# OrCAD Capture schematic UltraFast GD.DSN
size E
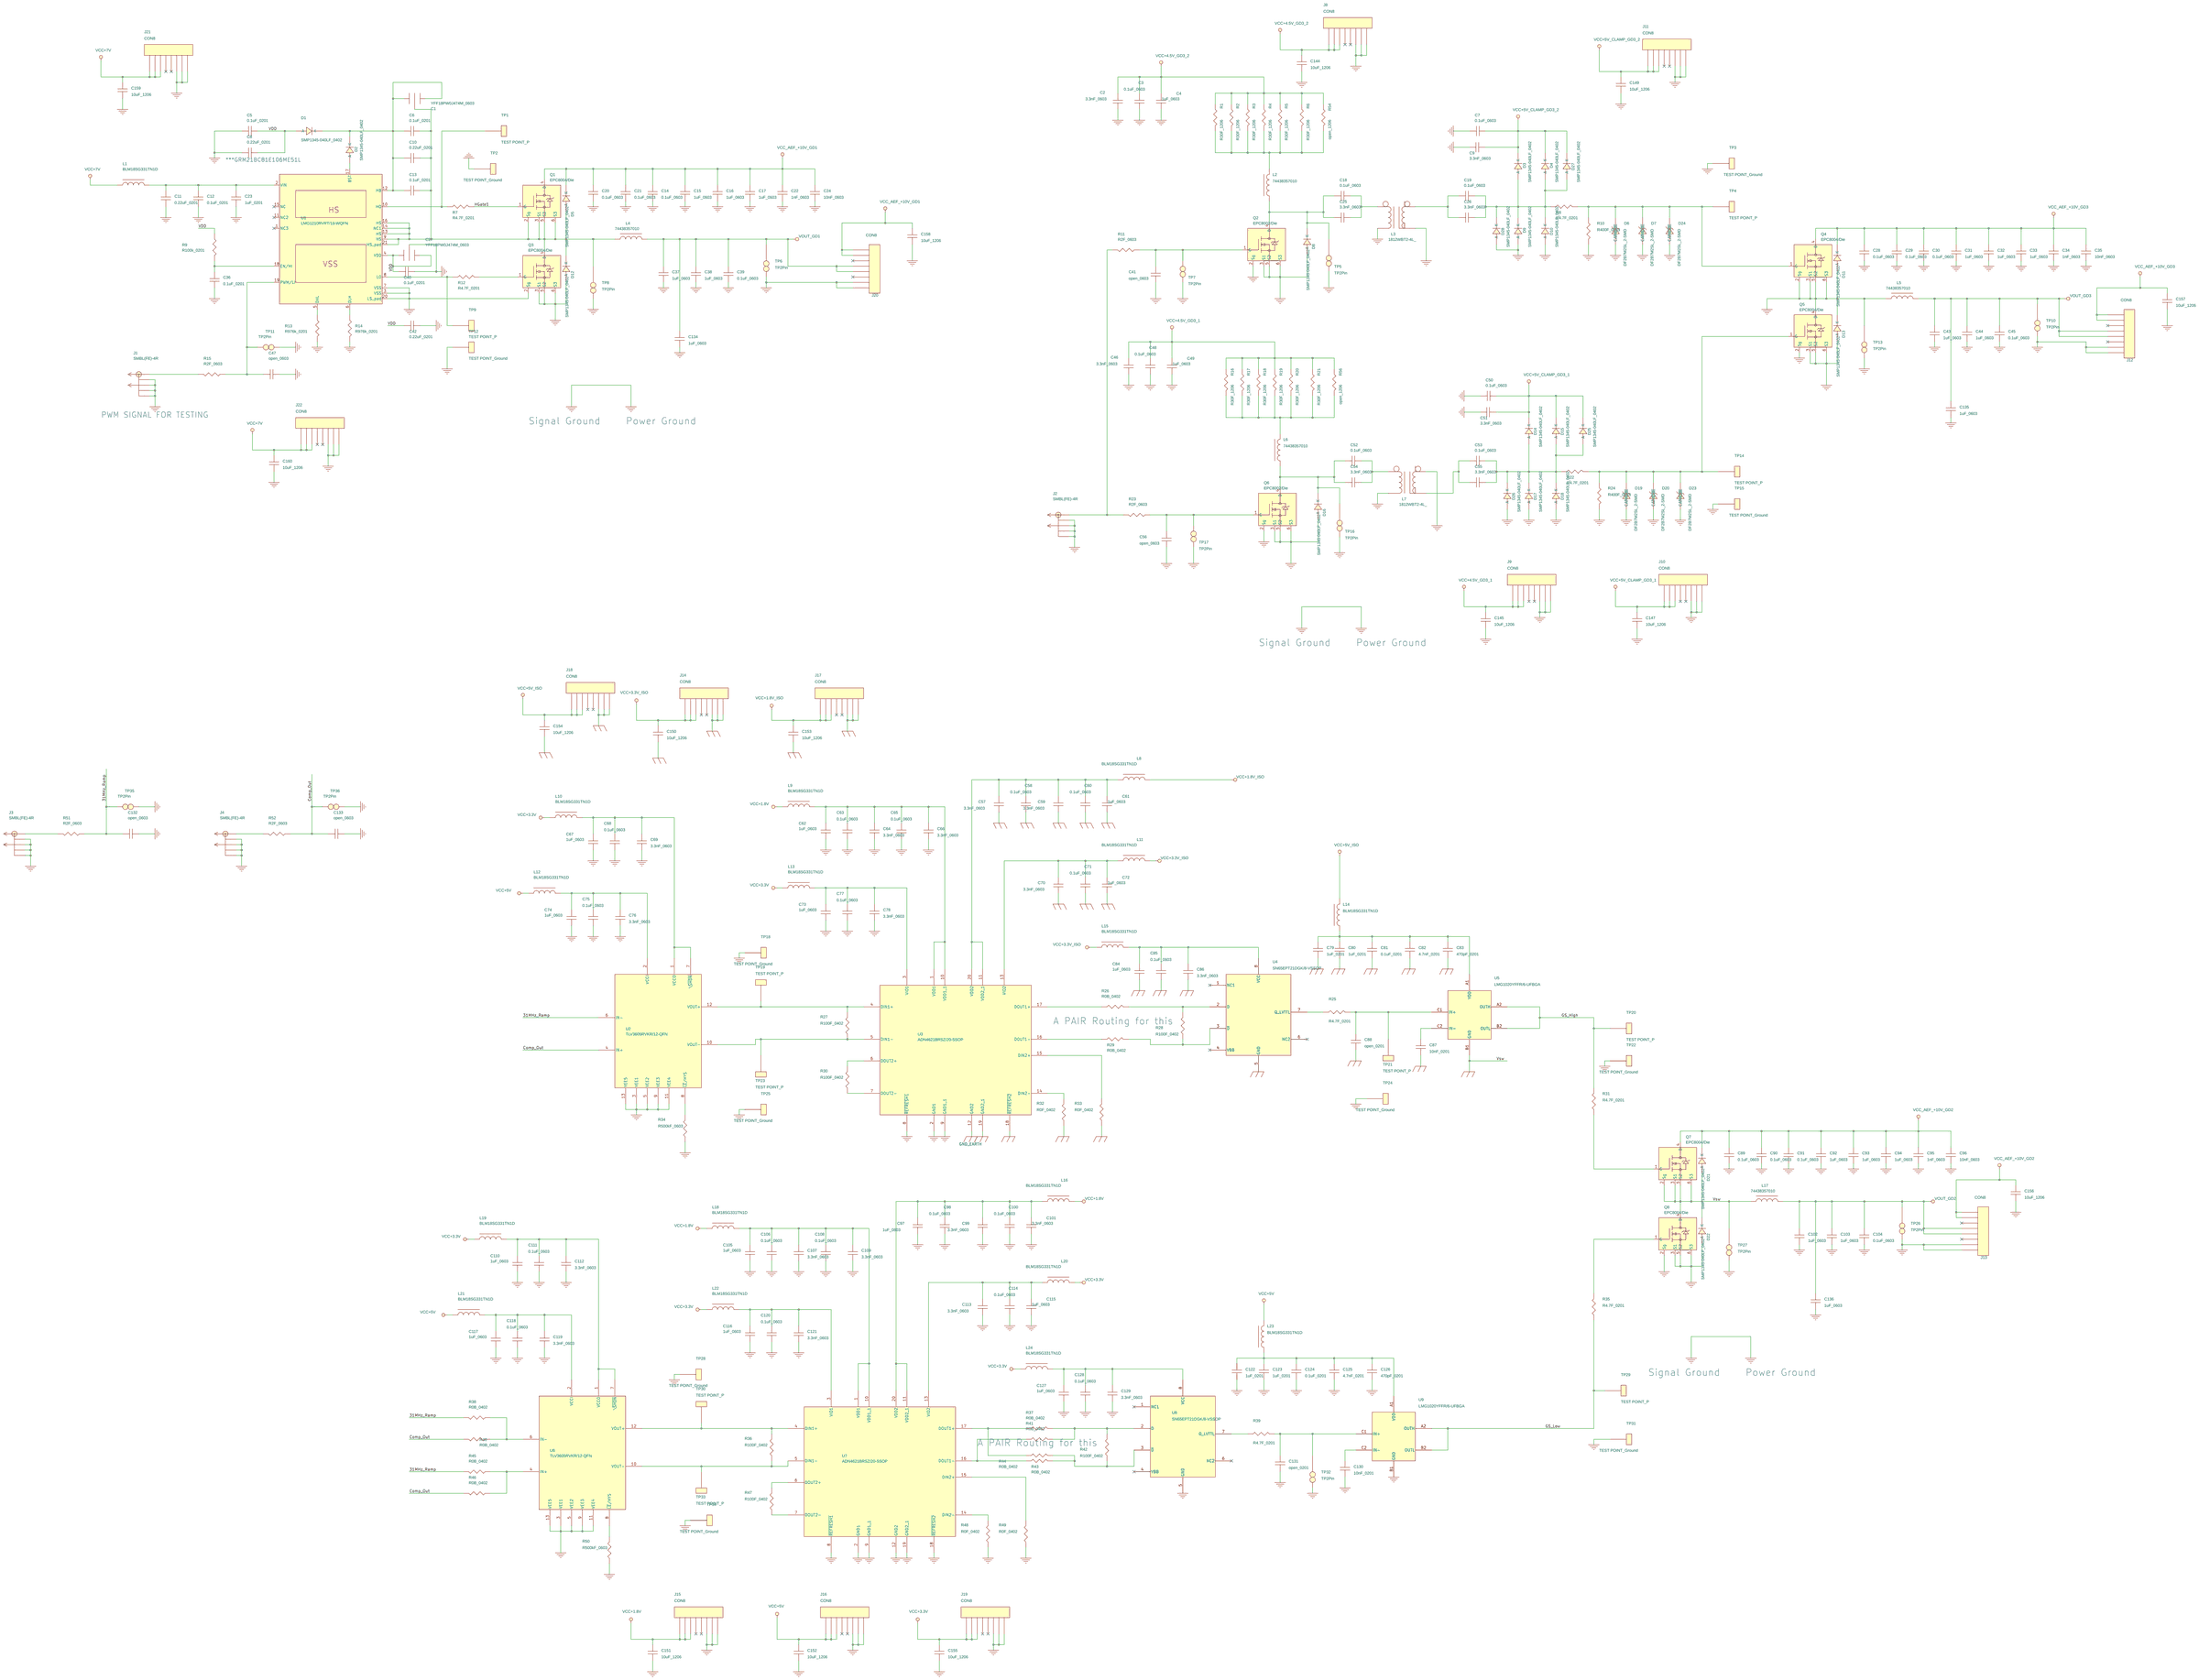
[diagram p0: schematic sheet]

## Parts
C1  YFF18PW0J474M_0603  [FEEDTHRU_0603]
C2  3.3nF_0603  [C1608]
C3  0.1uF_0603  [C1608]
C4  1uF_0603  [C1608]
C5  0.1uF_0201  [C_0201_SHORT]
C6  0.1uF_0201  [C_0201_SHORT]
C7  0.1uF_0603  [C1608]
C8  0.22uF_0201  [C_0201_SHORT]
C9  3.3nF_0603  [C1608]
C10  0.22uF_0201  [C_0201_SHORT]
C11  0.22uF_0201  [C_0201_SHORT]
C12  0.1uF_0201  [C_0201_SHORT]
C13  0.1uF_0201  [C_0201_SHORT]
C14  0.1uF_0603  [C1608]
C15  1uF_0603  [C1608]
C16  1uF_0603  [C1608]
C17  1uF_0603  [C1608]
C18  0.1uF_0603  [C1608]
C19  0.1uF_0603  [C1608]
C20  0.1uF_0603  [C1608]
C21  0.1uF_0603  [C1608]
C22  1nF_0603  [C1608]
C23  1uF_0201  [C_0201_SHORT]
C24  10nF_0603  [C1608]
C25  3.3nF_0603  [C1608]
C26  3.3nF_0603  [C1608]
C27  YFF18PW0J474M_0603  [FEEDTHRU_0603]
C28  0.1uF_0603  [C1608]
C29  0.1uF_0603  [C1608]
C30  0.1uF_0603  [C1608]
C31  1uF_0603  [C1608]
C32  1uF_0603  [C1608]
C33  1uF_0603  [C1608]
C34  1nF_0603  [C1608]
C35  10nF_0603  [C1608]
C36  0.1uF_0201  [C_0201_SHORT]
C37  1uF_0603  [C1608]
C38  1uF_0603  [C1608]
C39  0.1uF_0603  [C1608]
C40  0.1uF_0201  [C_0201_SHORT]
C41  open_0603  [C1608]
C42  0.22uF_0201  [C_0201_SHORT]
C43  1uF_0603  [C1608]
C44  1uF_0603  [C1608]
C45  0.1uF_0603  [C1608]
C46  3.3nF_0603  [C1608]
C47  open_0603  [C1608]
C48  0.1uF_0603  [C1608]
C49  1uF_0603  [C1608]
C50  0.1uF_0603  [C1608]
C51  3.3nF_0603  [C1608]
C52  0.1uF_0603  [C1608]
C53  0.1uF_0603  [C1608]
C54  3.3nF_0603  [C1608]
C55  3.3nF_0603  [C1608]
C56  open_0603  [C1608]
C57  3.3nF_0603  [C1608]
C58  0.1uF_0603  [C1608]
C59  3.3nF_0603  [C1608]
C60  0.1uF_0603  [C1608]
C61  1uF_0603  [C1608]
C62  1uF_0603  [C1608]
C63  0.1uF_0603  [C1608]
C64  3.3nF_0603  [C1608]
C65  0.1uF_0603  [C1608]
C66  3.3nF_0603  [C1608]
C67  1uF_0603  [C1608]
C68  0.1uF_0603  [C1608]
C69  3.3nF_0603  [C1608]
C70  3.3nF_0603  [C1608]
C71  0.1uF_0603  [C1608]
C72  1uF_0603  [C1608]
C73  1uF_0603  [C1608]
C74  1uF_0603  [C1608]
C75  0.1uF_0603  [C1608]
C76  3.3nF_0603  [C1608]
C77  0.1uF_0603  [C1608]
C78  3.3nF_0603  [C1608]
C79  1uF_0201  [C_0201_SHORT]
C80  1uF_0201  [C_0201_SHORT]
C81  0.1uF_0201  [C_0201_SHORT]
C82  4.7nF_0201  [C_0201_SHORT]
C83  470pF_0201  [C_0201_SHORT]
C84  1uF_0603  [C1608]
C85  0.1uF_0603  [C1608]
C86  3.3nF_0603  [C1608]
C87  10nF_0201  [C_0201_SHORT]
C88  open_0201  [C_0201_SHORT]
C89  0.1uF_0603  [C1608]
C90  0.1uF_0603  [C1608]
C91  0.1uF_0603  [C1608]
C92  1uF_0603  [C1608]
C93  1uF_0603  [C1608]
C94  1uF_0603  [C1608]
C95  1nF_0603  [C1608]
C96  10nF_0603  [C1608]
C97  1uF_0603  [C1608]
C98  0.1uF_0603  [C1608]
C99  3.3nF_0603  [C1608]
C100  0.1uF_0603  [C1608]
C101  3.3nF_0603  [C1608]
C102  1uF_0603  [C1608]
C103  1uF_0603  [C1608]
C104  0.1uF_0603  [C1608]
C105  1uF_0603  [C1608]
C106  0.1uF_0603  [C1608]
C107  3.3nF_0603  [C1608]
C108  0.1uF_0603  [C1608]
C109  3.3nF_0603  [C1608]
C110  1uF_0603  [C1608]
C111  0.1uF_0603  [C1608]
C112  3.3nF_0603  [C1608]
C113  3.3nF_0603  [C1608]
C114  0.1uF_0603  [C1608]
C115  1uF_0603  [C1608]
C116  1uF_0603  [C1608]
C117  1uF_0603  [C1608]
C118  0.1uF_0603  [C1608]
C119  3.3nF_0603  [C1608]
C120  0.1uF_0603  [C1608]
C121  3.3nF_0603  [C1608]
C122  1uF_0201  [C_0201_SHORT]
C123  1uF_0201  [C_0201_SHORT]
C124  0.1uF_0201  [C_0201_SHORT]
C125  4.7nF_0201  [C_0201_SHORT]
C126  470pF_0201  [C_0201_SHORT]
C127  1uF_0603  [C1608]
C128  0.1uF_0603  [C1608]
C129  3.3nF_0603  [C1608]
C130  10nF_0201  [C_0201_SHORT]
C131  open_0201  [C_0201_SHORT]
C132  open_0603  [C1608]
C133  open_0603  [C1608]
C134  1uF_0603  [C1608]
C135  1uF_0603  [C1608]
C136  1uF_0603  [C1608]
C144  10uF_1206  [OPEN_1206]
C145  10uF_1206  [OPEN_1206]
C147  10uF_1206  [OPEN_1206]
C149  10uF_1206  [OPEN_1206]
C150  10uF_1206  [OPEN_1206]
C151  10uF_1206  [OPEN_1206]
C152  10uF_1206  [OPEN_1206]
C153  10uF_1206  [OPEN_1206]
C154  10uF_1206  [OPEN_1206]
C155  10uF_1206  [OPEN_1206]
C156  10uF_1206  [OPEN_1206]
C157  10uF_1206  [OPEN_1206]
C158  10uF_1206  [OPEN_1206]
C159  10uF_1206  [OPEN_1206]
C160  10uF_1206  [OPEN_1206]
D1  SMP1345-040LF_0402  [SMP1345-040LF]
D2  SMP1345-040LF_0402  [SMP1345-040LF]
D3  SMP1345-040LF_0402  [SMP1345-040LF]
D4  SMP1345-040LF_0402  [SMP1345-040LF]
D5  SMP1345-040LF_0402  [SMP1345-040LF]
D6  DF2B7M2SL_2-SMD  [DF2B7M3SL_L3F]
D7  DF2B7M2SL_2-SMD  [DF2B7M3SL_L3F]
D8  SMP1345-040LF_0402  [SMP1345-040LF]
D9  SMP1345-040LF_0402  [SMP1345-040LF]
D10  SMP1345-040LF_0402  [SMP1345-040LF]
D11  SMP1345-040LF_0402  [SMP1345-040LF]
D12  SMP1345-040LF_0402  [SMP1345-040LF]
D13  SMP1345-040LF_0402  [SMP1345-040LF]
D14  SMP1345-040LF_0402  [SMP1345-040LF]
D15  SMP1345-040LF_0402  [SMP1345-040LF]
D16  SMP1345-040LF_0402  [SMP1345-040LF]
D17  SMP1345-040LF_0402  [SMP1345-040LF]
D18  SMP1345-040LF_0402  [SMP1345-040LF]
D19  DF2B7M2SL_2-SMD  [DF2B7M3SL_L3F]
D20  DF2B7M2SL_2-SMD  [DF2B7M3SL_L3F]
D21  SMP1345-040LF_0402  [SMP1345-040LF]
D22  SMP1345-040LF_0402  [SMP1345-040LF]
D23  DF2B7M2SL_2-SMD  [DF2B7M3SL_L3F]
D24  DF2B7M2SL_2-SMD  [DF2B7M3SL_L3F]
D25  SMP1345-040LF_0402  [SMP1345-040LF]
D26  SMP1345-040LF_0402  [SMP1345-040LF]
D27  SMP1345-040LF_0402  [SMP1345-040LF]
D28  SMP1345-040LF_0402  [SMP1345-040LF]
J1  SMBL(FE)-4R  [SMBL(FE)-4R]
J2  SMBL(FE)-4R  [SMBL(FE)-4R]
J3  SMBL(FE)-4R  [SMBL(FE)-4R]
J4  SMBL(FE)-4R  [SMBL(FE)-4R]
J8  CON8  [HEADER_8_2.54MM]
J9  CON8  [HEADER_8_2.54MM]
J10  CON8  [HEADER_8_2.54MM]
J11  CON8  [HEADER_8_2.54MM]
J12  CON8  [HEADER_8_2.54MM]
J13  CON8  [HEADER_8_2.54MM]
J14  CON8  [HEADER_8_2.54MM]
J15  CON8  [HEADER_8_2.54MM]
J16  CON8  [HEADER_8_2.54MM]
J17  CON8  [HEADER_8_2.54MM]
J18  CON8  [HEADER_8_2.54MM]
J19  CON8  [HEADER_8_2.54MM]
J20  CON8  [HEADER_8_2.54MM]
J21  CON8  [HEADER_8_2.54MM]
J22  CON8  [HEADER_8_2.54MM]
L1  BLM18SG331TN1D  [L1608]
L2  74438357010  [74438357010]
L3  1812WBT2-4L_  [1812WBT2]
L4  74438357010  [74438357010]
L5  74438357010  [74438357010]
L6  74438357010  [74438357010]
L7  1812WBT2-4L_  [1812WBT2]
L8  BLM18SG331TN1D  [L1608]
L9  BLM18SG331TN1D  [L1608]
L10  BLM18SG331TN1D  [L1608]
L11  BLM18SG331TN1D  [L1608]
L12  BLM18SG331TN1D  [L1608]
L13  BLM18SG331TN1D  [L1608]
L14  BLM18SG331TN1D  [L1608]
L15  BLM18SG331TN1D  [L1608]
L16  BLM18SG331TN1D  [L1608]
L17  74438357010  [74438357010]
L18  BLM18SG331TN1D  [L1608]
L19  BLM18SG331TN1D  [L1608]
L20  BLM18SG331TN1D  [L1608]
L21  BLM18SG331TN1D  [L1608]
L22  BLM18SG331TN1D  [L1608]
L23  BLM18SG331TN1D  [L1608]
L24  BLM18SG331TN1D  [L1608]
Q1  EPC8004/Die  [EPC8004/DIE_SILK]
Q2  EPC8002/Die  [EPC8004/DIE_SILK]
Q3  EPC8004/Die  [EPC8004/DIE_SILK]
Q4  EPC8004/Die  [EPC8004/DIE_SILK]
Q5  EPC8004/Die  [EPC8004/DIE_SILK]
Q6  EPC8002/Die  [EPC8004/DIE_SILK]
Q7  EPC8004/Die  [EPC8004/DIE_SILK]
Q8  EPC8004/Die  [EPC8004/DIE_SILK]
R1  R30F_1206  [(NU)287F_1206]
R2  R30F_1206  [(NU)287F_1206]
R3  R30F_1206  [(NU)287F_1206]
R4  R30F_1206  [(NU)287F_1206]
R5  R30F_1206  [(NU)287F_1206]
R6  R30F_1206  [(NU)287F_1206]
R7  R4.7F_0201  [R_0201_SHORT]
R8  R4.7F_0201  [R_0201_SHORT]
R9  R100k_0201  [R_0201_SHORT]
R10  R400F_0603  [R_1608]
R11  R2F_0603  [R_1608]
R12  R4.7F_0201  [R_0201_SHORT]
R13  R976k_0201  [R_0201_SHORT]
R14  R976k_0201  [R_0201_SHORT]
R15  R2F_0603  [R_1608]
R16  R30F_1206  [(NU)287F_1206]
R17  R30F_1206  [(NU)287F_1206]
R18  R30F_1206  [(NU)287F_1206]
R19  R30F_1206  [(NU)287F_1206]
R20  R30F_1206  [(NU)287F_1206]
R21  R30F_1206  [(NU)287F_1206]
R22  R4.7F_0201  [R_0201_SHORT]
R23  R2F_0603  [R_1608]
R24  R400F_0603  [R_1608]
R25  R4.7F_0201  [R_0201_SHORT]
R26  R0B_0402  [R_0402_SMALL]
R27  R100F_0402  [R_0402_SMALL]
R28  R100F_0402  [R_0402_SMALL]
R29  R0B_0402  [R_0402_SMALL]
R30  R100F_0402  [R_0402_SMALL]
R31  R4.7F_0201  [R_0201_SHORT]
R32  R0F_0402  [R_0402_SMALL]
R33  R0F_0402  [R_0402_SMALL]
R34  R500kF_0603  [R_1608]
R35  R4.7F_0201  [R_0201_SHORT]
R36  R100F_0402  [R_0402_SMALL]
R37  R0B_0402  [R_0402_SMALL]
R38  R0B_0402  [R_0402_SMALL]
R39  R4.7F_0201  [R_0201_SHORT]
R40  R0B_0402  [R_0402_SMALL]
R41  R0B_0402  [R_0402_SMALL]
R42  R100F_0402  [R_0402_SMALL]
R43  R0B_0402  [R_0402_SMALL]
R44  R0B_0402  [R_0402_SMALL]
R45  R0B_0402  [R_0402_SMALL]
R46  R0B_0402  [R_0402_SMALL]
R47  R100F_0402  [R_0402_SMALL]
R48  R0F_0402  [R_0402_SMALL]
R49  R0F_0402  [R_0402_SMALL]
R50  R500kF_0603  [R_1608]
R51  R2F_0603  [R_1608]
R52  R2F_0603  [R_1608]
R54  open_1206  [(NU)287F_1206]
R56  open_1206  [(NU)287F_1206]
TP1  TEST POINT_P  [TP1PIN_POS]
TP2  TEST POINT_Ground  [TP1PIN_NEG]
TP3  TEST POINT_Ground  [TP1PIN_NEG]
TP4  TEST POINT_P  [TP1PIN_POS]
TP5  TP2Pin  [TP2PIN]
TP6  TP2Pin  [TP2PIN]
TP7  TP2Pin  [TP2PIN]
TP8  TP2Pin  [TP2PIN]
TP9  TEST POINT_P  [TP1PIN_POS]
TP10  TP2Pin  [TP2PIN]
TP11  TP2Pin  [TP2PIN]
TP12  TEST POINT_Ground  [TP1PIN_NEG]
TP13  TP2Pin  [TP2PIN]
TP14  TEST POINT_P  [TP1PIN_POS]
TP15  TEST POINT_Ground  [TP1PIN_NEG]
TP16  TP2Pin  [TP2PIN]
TP17  TP2Pin  [TP2PIN]
TP18  TEST POINT_Ground  [TP1PIN_NEG]
TP19  TEST POINT_P  [TP1PIN_POS]
TP20  TEST POINT_P  [TP1PIN_POS]
TP21  TEST POINT_P  [TP1PIN_POS]
TP22  TEST POINT_Ground  [TP1PIN_NEG]
TP23  TEST POINT_P  [TP1PIN_POS]
TP24  TEST POINT_Ground  [TP1PIN_NEG]
TP25  TEST POINT_Ground  [TP1PIN_NEG]
TP26  TP2Pin  [TP2PIN]
TP27  TP2Pin  [TP2PIN]
TP28  TEST POINT_Ground  [TP1PIN_NEG]
TP29  TEST POINT_P  [TP1PIN_POS]
TP30  TEST POINT_P  [TP1PIN_POS]
TP31  TEST POINT_Ground  [TP1PIN_NEG]
TP32  TP2Pin  [TP2PIN]
TP33  TEST POINT_P  [TP1PIN_POS]
TP34  TEST POINT_Ground  [TP1PIN_NEG]
TP35  TP2Pin  [TP2PIN]
TP36  TP2Pin  [TP2PIN]
U1  LMG1210RVRT/19-WQFN  [LMG1210RVRT_SILK]
U2  TLV3605RVKR/12-QFN  [TLV3605RVKR/12-QFN]
U3  ADN4621BRSZ/20-SSOP  [ADN4621BRSZ/20-SSOP]
U4  SN65EPT21DGK/8-VSSOP  [SN65EPT21DGK/8-VSSOP]
U5  LMG1020YFFR/6-UFBGA  [LMG1020YFFR]
U6  TLV3605RVKR/12-QFN  [TLV3605RVKR/12-QFN]
U7  ADN4621BRSZ/20-SSOP  [ADN4621BRSZ/20-SSOP]
U8  SN65EPT21DGK/8-VSSOP  [SN65EPT21DGK/8-VSSOP]
U9  LMG1020YFFR/6-UFBGA  [LMG1020YFFR]

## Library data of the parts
C1 C27 = CAP_NP_0
C2-C13 C18 C19 C23 C25 C26 C36 C40-C42 C46-C88 C97-C101 C105-C133 = CAP_NP_1
C14-C17 C20-C22 C24 C28-C35 C37-C39 C43-C45 C89-C96 C102-C104 C134-C136 C144 C145 C147 C149-C160 = CAP_NP_1: PART NO: 151273
D1-D5 D8-D18 D21 D22 D25-D28 = DIODE_1
D6 D7 D19 D20 D23 D24 = DIODE_ZENER_0: PART NO: 40002129
J1-J4 = 142-0701-506_0
J8-J22 = CON8
L1 L8-L16 L18-L24 = CHOKE_1_v2
L2 L4-L6 L17 = INDUCTOR_4
L3 L7 = INDUCTOR_0
Q1-Q8 = IRFZ24N_TO_2: PATH NO: 1063683
R1-R6 R16-R21 R54 R56 = R_0: PART NO: 1044274
R7-R15 R22-R52 = R_0
TP1-TP4 TP9 TP12 TP14 TP15 TP18-TP25 TP28-TP31 TP33 TP34 = TEST_POINT
TP5-TP8 TP10 TP11 TP13 TP16 TP17 TP26 TP27 TP32 TP35 TP36 = T_POINT_R_1
U1 = CON20A_5
U2 = CON8A_15
U3 U7 = CON8A_12
U4 U8 = CON8A_11
U5 U9 = CON8A_10
U6 = CON8A_16

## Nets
GND_EARTH: C57.1 C58.1 C59.1 C60.1 C61.1 C70.1 C71.1 C72.1 C79.2 C80.2 C81.2 C82.2 C83.2 C84.1 C85.1 C86.1 C87.2 C88.2 C150.2 C153.2 C154.2 D21.1(A) D22.2(K) J14.6 J14.7 J14.8 J17.6 J17.7 J17.8 J18.6 J18.7 J18.8 L17.1 Q7.2(Sg) Q7.3(S1) Q7.5(S2) Q7.6(S3) Q8.4(D) R32.2 R33.2 TP27.1(TP) U3.12(GND2) U3.18(~{REFRESH2}) U3.19(GND2_1) U4.5(GND) U5.B1(GND)
GND_POWER: C5.2 C8.2 C11.2 C12.2 C14.2 C15.2 C16.2 C17.2 C20.2 C21.2 C22.2 C23.2 C24.2 C27.3 C36.1 C37.2 C38.2 C39.2 C40.1 C42.1 C47.1 C134.2 C158.2 C159.2 C160.2 D12.1(A) J1.2 J1.3 J1.4 J1.5 J20.7 J20.8 J21.6 J21.7 J21.8 J22.6 J22.7 J22.8 Q3.2(Sg) Q3.3(S1) Q3.5(S2) Q3.6(S3) R13.1 R14.1 TP2.1 TP6.2(GND) TP8.2(GND) TP11.2(GND) TP12.1 U1.3(VSS) U1.7(VSS) U1.20(LS_pad)
Vcc+1.8V: C151.1 J15.1 J15.2 J15.3 L9.1 L16.1 L18.1
Vcc+1.8V_ISO: C153.1 J17.1 J17.2 J17.3 L8.1
Vcc+3.3V: C155.1 J19.1 J19.2 J19.3 L10.1 L13.1 L19.1 L20.1 L22.1 L24.1
Vcc+3.3V_ISO: C150.1 J14.1 J14.2 J14.3 L11.1 L15.1
Vcc+4.5V_GD3_1: C46.2 C48.2 C49.2 C145.1 J9.1 J9.2 J9.3 R16.2 R17.2 R18.2 R19.2 R20.2 R21.2 R56.2
Vcc+4.5V_GD3_2: C2.2 C3.2 C4.2 C144.1 J8.1 J8.2 J8.3 R1.2 R2.2 R3.2 R4.2 R5.2 R6.2 R54.2
Vcc+5V: C152.1 J16.1 J16.2 J16.3 L12.1 L21.1 L23.2
Vcc+5V_Clamp_GD3_1: C50.1 C51.2 C147.1 D14.2(K) D15.2(K) D25.2(K) J10.1 J10.2 J10.3
Vcc+5V_Clamp_GD3_2: C7.1 C9.2 C149.1 D3.2(K) D4.2(K) D27.2(K) J11.1 J11.2 J11.3
Vcc+5V_ISO: C154.1 J18.1 J18.2 J18.3 L14.2
Vcc+7V: C159.1 C160.1 J21.1 J21.2 J21.3 J22.1 J22.2 J22.3 L1.1
Vcc_AEF_+10V_GD1: C14.1 C15.1 C16.1 C17.1 C20.1 C21.1 C22.1 C24.1 C158.1 D5.2(K) J20.1 J20.2 Q1.4(D)
Vcc_AEF_+10V_GD2: C89.1 C90.1 C91.1 C92.1 C93.1 C94.1 C95.1 C96.1 C156.1 D21.2(K) J13.1 J13.2 Q7.4(D)
Vcc_AEF_+10V_GD3: C28.1 C29.1 C30.1 C31.1 C32.1 C33.1 C34.1 C35.1 C157.1 D11.2(K) J12.1 J12.2 Q4.4(D)
VDD: C5.1 C8.1 C27.1 C27.2 C40.2 C42.2 D1.1(A) R9.2 U1.4(VDD)
1: C62.1 C63.1 C64.1 C65.1 C66.1 C67.1 C68.1 C69.1 C73.1 C74.1 C75.1 C76.1 C77.1 C78.1 C89.2 C90.2 C91.2 C92.2 C93.2 C94.2 C95.2 C96.2 C97.1 C98.1 C99.1 C100.1 C101.1 C102.2 C103.2 C104.2 C105.1 C106.1 C107.1 C108.1 C109.1 C110.1 C111.1 C112.1 C113.1 C114.1 C115.1 C116.1 C117.1 C118.1 C119.1 C120.1 C121.1 C122.2 C123.2 C124.2 C125.2 C126.2 C127.1 C128.1 C129.1 C130.2 C131.2 C132.1 C133.1 C136.2 C151.2 C152.2 C155.2 C156.2 D22.1(A) J3.2 J3.3 J3.4 J3.5 J4.2 J4.3 J4.4 J4.5 J13.7 J13.8 J15.6 J15.7 J15.8 J16.6 J16.7 J16.8 J19.6 J19.7 J19.8 Q8.2(Sg) Q8.3(S1) Q8.5(S2) Q8.6(S3) R34.2 R48.2 R49.2 R50.2 TP18.1 TP22.1 TP24.1 TP25.1 TP26.2(GND) TP27.2(GND) TP28.1 TP31.1 TP32.2(GND) TP34.1 TP35.2(GND) TP36.2(GND) U2.3(VEE1) U2.5(VEE2) U2.9(VEE3) U2.11(VEE4) U2.13(VEE5) U3.2(GND1) U3.8(~{REFRESH1}) U3.9(GND1_1) U6.3(VEE1) U6.5(VEE2) U6.9(VEE3) U6.11(VEE4) U6.13(VEE5) U7.2(GND1) U7.8(~{REFRESH1}) U7.9(GND1_1) U7.12(GND2) U7.18(~{REFRESH2}) U7.19(GND2_1) U8.5(GND) U9.B1(GND)
4: C2.1 C3.1 C4.1 C28.2 C29.2 C30.2 C31.2 C32.2 C33.2 C34.2 C35.2 C41.1 C43.2 C44.2 C45.2 C46.1 C48.1 C49.1 C50.2 C51.1 C56.1 C135.2 C144.2 C145.2 C147.2 C157.2 D8.1(A) D13.1(A) D16.1(A) D17.1(A) D18.1(A) D19.1(ANODE) D20.1(ANODE) D23.1(ANODE) D26.1(A) J2.2 J2.3 J2.4 J2.5 J8.6 J8.7 J8.8 J9.6 J9.7 J9.8 J10.6 J10.7 J10.8 J12.7 J12.8 L3.3 L7.1 L7.3 Q2.2(Sg) Q2.3(S1) Q2.5(S2) Q2.6(S3) Q5.2(Sg) Q5.3(S1) Q5.5(S2) Q5.6(S3) Q6.2(Sg) Q6.3(S1) Q6.5(S2) Q6.6(S3) R24.1 TP3.1 TP5.2(GND) TP7.2(GND) TP10.2(GND) TP13.2(GND) TP15.1 TP16.2(GND) TP17.2(GND)
5: C7.2 C9.1 C149.2 D6.1(ANODE) D7.1(ANODE) D9.1(A) D10.1(A) D11.1(A) D13.2(K) D24.1(ANODE) D28.1(A) J11.6 J11.7 J11.8 L3.2 L5.1 Q4.2(Sg) Q4.3(S1) Q4.5(S2) Q4.6(S3) Q5.4(D) R10.1 TP13.1(TP)
31MHz_Ramp: C132.2 R38.1 R45.1 R51.2 TP35.1(TP) U2.6(IN-)
Comp_Out: C133.2 R40.1 R46.1 R52.2 TP36.1(TP) U2.4(IN+)
GS_High: R31.1 TP20.1 U5.A2(OUTH) U5.B2(OUTL)
GS_Low: R35.2 TP29.1 U9.A2(OUTH) U9.B2(OUTL)
HGate1: Q1.1(G) R7.1
Vout_GD1: C37.1 C38.1 C39.1 C134.1 J20.4 J20.5 L4.2 TP6.1(TP)
Vout_GD2: C102.1 C103.1 C104.1 C136.1 J13.4 J13.5 L17.2 TP26.1(TP)
Vout_GD3: C43.1 C44.1 C45.1 C135.1 J12.4 J12.5 L5.2 TP10.1(TP)
N14344006: J1.1 R15.1
N14345346: C1.3 C6.1 C10.1 C13.1 D5.1(A) D12.2(K) L4.1 Q1.2(Sg) Q1.3(S1) Q1.5(S2) Q1.6(S3) Q3.4(D) TP8.1(TP) U1.9(HS) U1.13(HS) U1.14(NC1) U1.16(HS) U1.21(HS_pad)
N14372495: C47.2 R15.2 TP11.1(TP) U1.19(PWM/LI)
N14376814: R13.2 U1.5(DHL)
N14376818: R14.2 U1.6(DLH)
N14376850: Q3.1(G) R12.1
N14377848: R12.2 TP9.1 U1.8(LO)
N14377884: R7.2 TP1.1 U1.10(HO)
N14378663: C1.1 C1.2 C6.2 C10.2 C13.2 D1.2(K) D2.2(K) U1.12(HB)
N14384475: C11.1 C12.1 C23.1 L1.2 U1.2(VIN)
N14385796: C36.2 R9.1 U1.18(EN/HI)
N14555005: D2.1(A) U1.17(BST)
N15502076: C57.2 C58.2 C59.2 C60.2 C61.2 L8.2 U3.11(VDD2_1) U3.20(VDD2)
N15502526: C62.2 C63.2 C64.2 C65.2 C66.2 L9.2 U3.1(VDD1) U3.10(VDD1_1)
N15502606: C67.2 C68.2 C69.2 L10.2 U2.1(VCCO) U2.7(\~{SHDN})
N15502892: C70.2 C71.2 C72.2 L11.2 U3.13(VIO2)
N15503050: C73.2 C77.2 C78.2 L13.2 U3.3(VIO1)
N15503086: C74.2 C75.2 C76.2 L12.2 U2.2(VCCI)
N15503304: C79.1 C80.1 C81.1 C82.1 C83.1 L14.1 U5.A1(VDD)
N15503430: C84.2 C85.2 C86.2 L15.2 U4.8(VCC)
N15503842: R27.1 TP19.1 U2.12(VOUT+) U3.4(DIN1+)
N15503854: R26.2 U3.17(DOUT1+)
N15503858: R26.1 R28.1 U4.2(D)
N15503896: R25.2 U4.7(Q_LVTTL)
N15503900: C88.1 R25.1 TP21.1 U5.C1(IN+)
N15503962: R28.2 R29.1 U4.3(~{D})
N15503966: C87.1 U5.C2(IN-)
N15504004: R27.2 TP23.1 U2.10(VOUT-) U3.5(DIN1-)
N15504016: R29.2 U3.16(DOUT1-)
N15504106: R33.1 U3.15(DIN2+)
N15504122: R30.1 U3.6(DOUT2+)
N15504182: R30.2 U3.7(DOUT2-)
N15504186: R32.1 U3.14(DIN2-)
N15504214: R34.1 U2.8(~{LE}/HYS)
N15504410: C97.2 C98.2 C99.2 C100.2 C101.2 L16.2 U7.11(VDD2_1) U7.20(VDD2)
N15504600: C105.2 C106.2 C107.2 C108.2 C109.2 L18.2 U7.1(VDD1) U7.10(VDD1_1)
N15504680: C110.2 C111.2 C112.2 L19.2 U6.1(VCCO) U6.7(\~{SHDN})
N15504966: C113.2 C114.2 C115.2 L20.2 U7.13(VIO2)
N15505124: C116.2 C120.2 C121.2 L22.2 U7.3(VIO1)
N15505160: C117.2 C118.2 C119.2 L21.2 U6.2(VCCI)
N15505378: C122.1 C123.1 C124.1 C125.1 C126.1 L23.1 U9.A1(VDD)
N15505504: C127.2 C128.2 C129.2 L24.2 U8.8(VCC)
N15506000: R38.2 R40.2 U6.6(IN-)
N15506062: R36.1 TP30.1 U6.12(VOUT+) U7.4(DIN1+)
N15506074: R37.2 R44.2 U7.17(DOUT1+)
N15506086: R37.1 R41.1 R42.1 U8.2(D)
N15506172: R39.2 U8.7(Q_LVTTL)
N15506176: C131.1 R39.1 TP32.1(TP) U9.C1(IN+)
N15506248: R41.2 R43.2 U7.16(DOUT1-)
N15506296: R42.2 R43.1 R44.1 U8.3(~{D})
N15506300: C130.1 U9.C2(IN-)
N15506350: R36.2 TP33.1 U6.10(VOUT-) U7.5(DIN1-)
N15506450: R45.2 R46.2 U6.4(IN+)
N15506482: R49.1 U7.15(DIN2+)
N15506498: R47.1 U7.6(DOUT2+)
N15506572: R47.2 U7.7(DOUT2-)
N15506576: R48.1 U7.14(DIN2-)
N15506604: R50.1 U6.8(~{LE}/HYS)
N15510005: Q7.1(G) R31.2
N15516326: Q8.1(G) R35.1
N15530378: J3.1 R51.1
N15530777: J4.1 R52.1
N15533464: C56.2 Q6.1(G) R23.2 TP17.1(TP)
N15533544: J2.1 R11.1 R23.1
N15534438: C52.2 C54.2 D16.2(K) L6.1 Q6.4(D) TP16.1(TP)
N15540340: L6.2 R16.1 R17.1 R18.1 R19.1 R20.1 R21.1 R56.1
N15542400: C52.1 C54.1 L7.4
N15544818: C53.2 C55.2 L7.2
N15544826: C53.1 C55.1 D14.1(A) D15.1(A) D17.2(K) D18.2(K) D25.1(A) D26.2(K) R22.2
N15548241: D19.2(CATHODE) D20.2(CATHODE) D23.2(CATHODE) Q5.1(G) R22.1 R24.2 TP14.1
N15557493: L2.2 R1.1 R2.1 R3.1 R4.1 R5.1 R6.1 R54.1
N15557657: C19.1 C26.1 D3.1(A) D4.1(A) D9.2(K) D10.2(K) D27.1(A) D28.2(K) R8.2
N15557701: C18.2 C25.2 D8.2(K) L2.1 Q2.4(D) TP5.1(TP)
N15557709: C18.1 C25.1 L3.4
N15557717: C19.2 C26.2 L3.1
N15557829: D6.2(CATHODE) D7.2(CATHODE) D24.2(CATHODE) Q4.1(G) R8.1 R10.2 TP4.1
N15558199: C41.2 Q2.1(G) R11.2 TP7.1(TP)

Not connected (* = marked no-connect by the designer): J8 4* 5*; J9 4* 5*; J10 4* 5*; J11 4* 5*; J12 3* 6*; J13 3* 6*; J14 4* 5*; J15 4* 5*; J16 4* 5*; J17 4* 5*; J18 4* 5*; J19 4* 5*; J20 3* 6*; J21 4* 5*; J22 4* 5*; U1 1(NC3)* 11(NC2)* 15(NC)*; U4 1(NC1)* 4(VBB)* 6(NC2)*; U8 1(NC1)* 4(VBB)* 6(NC2)*

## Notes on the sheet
- ***GRM21BC81E106ME51L
- PWM SIGNAL FOR TESTING
- Signal Ground
- Power Ground
- Signal Ground
- Power Ground
- A PAIR Routing for this
- Signal Ground
- Power Ground
- A PAIR Routing for this
